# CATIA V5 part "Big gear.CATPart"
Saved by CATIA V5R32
Part number: Part2
Bounding box of the stored display mesh (mm): x -27.5 to 27.5, y -27.5 to 27.5, z 0 to 10
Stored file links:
  D:\PROJECTS\Project 2022\CATIA V5 6R 2022\Resources\Part Files\c16_catia_v5_6r2022_prt\Gear Joint-(16-53)\Big gear.CATPart
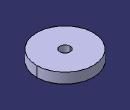
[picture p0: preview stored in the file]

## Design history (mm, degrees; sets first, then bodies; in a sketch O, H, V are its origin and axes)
Body1 (main body)
  Sketch1 on xy-plane, origin (0, 0, 0), H (1, 0, 0), V (0, 1, 0)
    circle A1 centre (0, 0) radius 27.5
    circle A2 centre (0, 0) radius 5
    radius A1 = 27.5
    radius A2 = 5
  Pad1: profile Sketch1, direction (0, 0, 1), length 10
